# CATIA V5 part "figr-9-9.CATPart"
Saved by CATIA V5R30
Part number: Part1
Bounding box of the stored display mesh (mm): x -15.705 to 88.369, y 0 to 286.83, z -20.723 to 20.723
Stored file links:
  D:\PROJECTS\CATIA V56R 2020\Resources\Parts File\c09_catia_v5_6r2020_prt\figr-9-9.CATPart
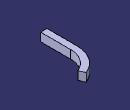
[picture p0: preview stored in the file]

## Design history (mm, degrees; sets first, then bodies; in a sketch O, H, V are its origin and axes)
Body1 (main body)
  Sketch1 on xy-plane, origin (0, 0, 0), H (1, 0, 0), V (0, 1, 0)
    line L1 (0, 0) -> (0, 150)
    arc A1 centre (131.8599, 150) radius 131.8599 from (0, 150) to (82.4884, 272.2681) cw
    length L1 = 150
    tangency: A1 L1
  Sketch2 on zx-plane, origin (0, 0, 0), H (-1, 0, 0), V (0, 0, 1)
    line L1 (15.7048, 20.7231) -> (15.7048, -20.7231)
    line L2 (15.7048, -20.7231) -> (-15.7048, -20.7231)
    line L3 (-15.7048, -20.7231) -> (-15.7048, 20.7231)
    line L4 (-15.7048, 20.7231) -> (15.7048, 20.7231)
    vertical: L1 V, L3 V
    horizontal: L2 H, L4 H
    equidistance: L1 L3 O, L2 L4 O
  Rib1: profile Sketch2, centre curve Sketch1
